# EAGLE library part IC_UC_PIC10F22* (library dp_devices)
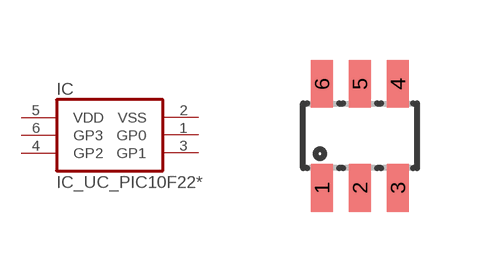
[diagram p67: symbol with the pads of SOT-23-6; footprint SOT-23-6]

Designator prefix IC

## IC_UC_PIC10F22  [SOT-23-6]
1  GP0
2  VSS  pwr
3  GP1
4  GP2
5  VDD  pwr
6  GP3

## Footprint SOT-23-6 (pad centres in mm)
smd 0.55 x 1.2: 1 -0.95,-1.3; 2 0,-1.3; 3 0.95,-1.3; 4 0.95,1.3; 5 0,1.3; 6 -0.95,1.3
